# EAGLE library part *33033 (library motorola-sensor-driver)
Brushless DC Motor Controller http://onsemi.com; mc33033-d.pdf
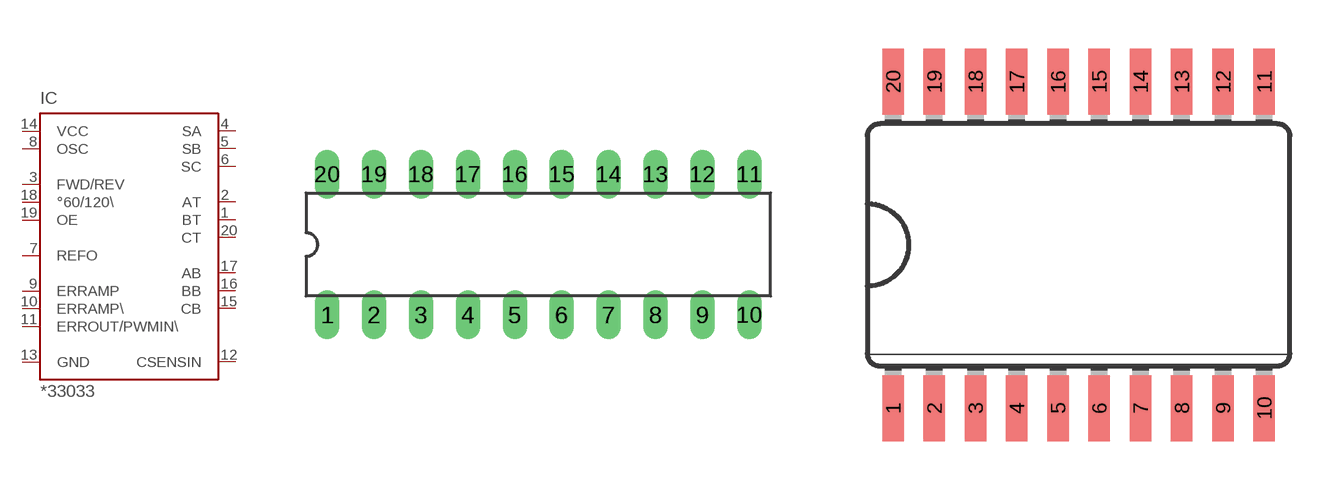
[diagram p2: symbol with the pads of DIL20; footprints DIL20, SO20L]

Designator prefix IC

## MC33033P  [DIL20]
1  BT  out
2  AT  out
3  FWD/REV  in
4  SA  in
5  SB  in
6  SC  in
7  REFO  out
8  OSC  in
9  ERRAMP  in
10  ERRAMP\  in
11  ERROUT/PWMIN\  pas
12  CSENSIN  in
13  GND  pwr
14  VCC  pwr
15  CB  out
16  BB  out
17  AB  out
18  °60/120\  in
19  OE  in
20  CT  out

## MC33033DW, NCV33033DW  [SO20L]
Pads as for DIL20

## Footprint DIL20 (pad centres in mm)
Dual In Line
drill 0.813 long: 1 -11.43,-3.81; 2 -8.89,-3.81; 3 -6.35,-3.81; 4 -3.81,-3.81; 5 -1.27,-3.81; 6 1.27,-3.81; 7 3.81,-3.81; 8 6.35,-3.81; 9 8.89,-3.81; 10 11.43,-3.81; 11 11.43,3.81; 12 8.89,3.81; 13 6.35,3.81; 14 3.81,3.81; 15 1.27,3.81; 16 -1.27,3.81; 17 -3.81,3.81; 18 -6.35,3.81; 19 -8.89,3.81; 20 -11.43,3.81

## Footprint SO20L (pad centres in mm)
Small Outline Package
smd 0.66 x 2.032: 1 -5.715,-5.029; 2 -4.445,-5.029; 3 -3.175,-5.029; 4 -1.905,-5.029; 5 -0.635,-5.029; 6 0.635,-5.029; 7 1.905,-5.029; 8 3.175,-5.029; 9 4.445,-5.029; 10 5.715,-5.029; 11 5.715,5.029; 12 4.445,5.029; 13 3.175,5.029; 14 1.905,5.029; 15 0.635,5.029; 16 -0.635,5.029; 17 -1.905,5.029; 18 -3.175,5.029; 19 -4.445,5.029; 20 -5.715,5.029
